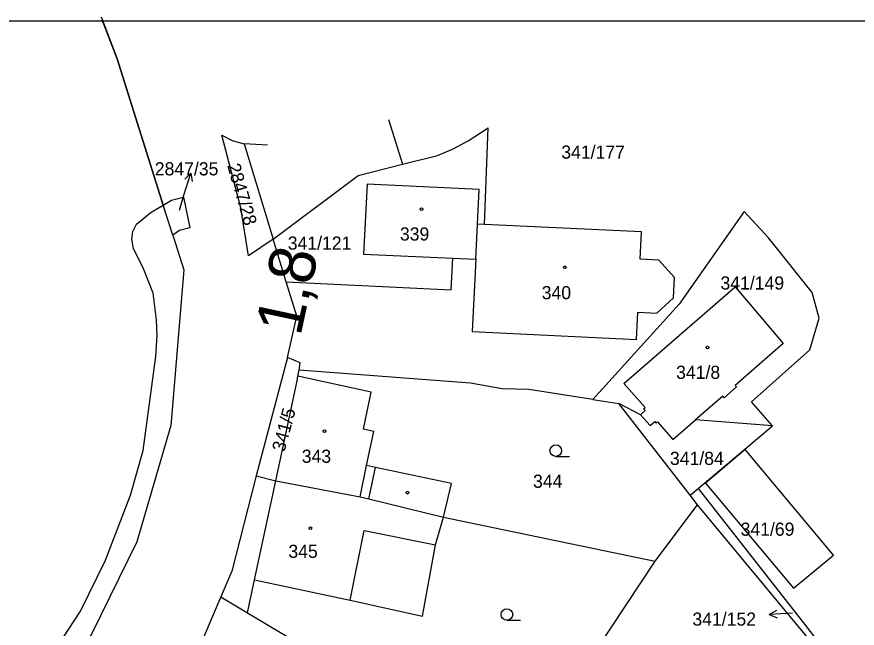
# Model space of a CAD drawing. Extents: x -558358 to -557517, y -1073786 to -1073189.
# Drawn here: x -558018.3 to -557909.7, y -1073268.6 to -1073189.6 of the extents above; entities that cross this region are included whole.
import ezdxf

# ---------------------------------------------------------------- set-up
doc = ezdxf.new("R2010")
doc.units = 0
for name, color, linetype in [('Hranice parcel', 7, 'Continuous'), ('Návěst místo trati', 7, 'Continuous'), ('Parcelní čísla', 7, 'Continuous'), ('Pop  PČ popisy', 7, 'Continuous'), ('Svazek obcí údolí Desné', 7, 'Continuous'), ('Vnitřní kresba', 7, 'Continuous'), ('Vrstva 1', 7, 'Continuous'), ('Značky budov', 7, 'Continuous'), ('Značky kultur', 7, 'Continuous')]:
    doc.layers.add(name, color=color, linetype=linetype)

msp = doc.modelspace()

# ---------------------------------------------------------------- linework, layer by layer
at = {"layer": 'Hranice parcel'}
for p, q in [((-557970.23, -1073202.86), (-557968.43, -1073208.63)), ((-557957.84, -1073216.4), (-557957.38, -1073203.94)), ((-557990.44, -1073205.56), (-557988.88, -1073205.99)), ((-557988.88, -1073205.99), (-557985.13, -1073218.31)), ((-557985.87, -1073206.17), (-557988.88, -1073205.99)), ((-557974.16, -1073210.07), (-557968.43, -1073208.63)), ((-557985.13, -1073218.31), (-557974.16, -1073210.07)), ((-557999.34, -1073213.91), (-557998.27, -1073213.29)), ((-558000.9, -1073214.81), (-557999.34, -1073213.91)), ((-557998.11, -1073217.81), (-557999.34, -1073213.91)), ((-557924.3, -1073214.73), (-557932.67, -1073226.72)), ((-557958.95, -1073220.92), (-557958.74, -1073216.36)), ((-557957.84, -1073216.4), (-557958.74, -1073216.36)), ((-557997.23, -1073217.21), (-557998.11, -1073217.81)), ((-557985.13, -1073218.31), (-557988.34, -1073220.45)), ((-557983.46, -1073223.81), (-557985.13, -1073218.31)), ((-557961.95, -1073220.78), (-557958.95, -1073220.92)), ((-557932.67, -1073226.72), (-557943.85, -1073239.02)), ((-557983.29, -1073233.62), (-557987.36, -1073248.89)), ((-557981.96, -1073236.04), (-557981.79, -1073235.24)), ((-557943.85, -1073239.02), (-557940.47, -1073239.54)), ((-557931.28, -1073251.41), (-557940.47, -1073239.54)), ((-557937.69, -1073241), (-557940.47, -1073239.54)), ((-557920.64, -1073242.45), (-557930.56, -1073241.68)), ((-557930.24, -1073250.53), (-557920.64, -1073242.45)), ((-557987.36, -1073248.89), (-557984.8, -1073249.54)), ((-557931.28, -1073251.41), (-557930.24, -1073250.53)), ((-557930.32, -1073252.64), (-557931.28, -1073251.41)), ((-557935.78, -1073259.94), (-557930.32, -1073252.64)), ((-557909.08, -1073278.25), (-557930.32, -1073252.64)), ((-557963.13, -1073254.23), (-557935.78, -1073259.94)), ((-557954.2, -1073287.72), (-557935.78, -1073259.94)), ((-557991.89, -1073264.55), (-557994.13, -1073269.82)), ((-557991.89, -1073264.55), (-557988.45, -1073266.61)), ((-557988.45, -1073266.61), (-557978.88, -1073272.32))]:
    msp.add_line(p, q, dxfattribs=at)
for points in [[(-558007.39, -1073189.57), (-558005.3, -1073194.99), (-557999.34, -1073213.91)], [(-557988.34, -1073220.45), (-557989.32, -1073214.27), (-557991.8, -1073204.87), (-557990.44, -1073205.56)], [(-557968.43, -1073208.63), (-557963.9, -1073207.49), (-557961.96, -1073206.66), (-557959.95, -1073205.6), (-557957.38, -1073203.94)], [(-557958.74, -1073216.36), (-557958.53, -1073211.88), (-557973.01, -1073211.21), (-557973.48, -1073220.25), (-557961.95, -1073220.78)], [(-557998.27, -1073213.29), (-557996.72, -1073212.87), (-557995.91, -1073216.87), (-557997.23, -1073217.21)], [(-557920.64, -1073242.45), (-557923.35, -1073239.36), (-557915.81, -1073232.62), (-557914.61, -1073228.54), (-557915.51, -1073225.19), (-557921.13, -1073218.15), (-557924.3, -1073214.73)], [(-557958.95, -1073220.92), (-557959.44, -1073230.26), (-557938.22, -1073231.3), (-557938.05, -1073227.77), (-557935.56, -1073227.89), (-557933.42, -1073225.91), (-557933.29, -1073223.26), (-557935.3, -1073221.04), (-557937.72, -1073220.92), (-557937.55, -1073217.37), (-557957.84, -1073216.4)], [(-557998.11, -1073217.81), (-557996.7, -1073222.28), (-557998.38, -1073242.39), (-558002.78, -1073257.43), (-558008.62, -1073269.37), (-558024.06, -1073293.44), (-558032.02, -1073303.96), (-558033.31, -1073305.78)], [(-557983.46, -1073223.81), (-557962.16, -1073224.87), (-557961.95, -1073220.78)], [(-557983.29, -1073233.62), (-557982.1, -1073228.28), (-557983.46, -1073223.81)], [(-557937.69, -1073241), (-557937.08, -1073240.47), (-557937.28, -1073240.24), (-557937.09, -1073240.08), (-557939.85, -1073236.97), (-557925.45, -1073224.49), (-557919.26, -1073231.82), (-557925.44, -1073237.21), (-557925.27, -1073237.41), (-557926.88, -1073238.81), (-557927.05, -1073238.61), (-557930.56, -1073241.68)], [(-557981.79, -1073235.24), (-557981.67, -1073234.3), (-557983.29, -1073233.62)], [(-557943.85, -1073239.02), (-557952.12, -1073237.75), (-557955.56, -1073237.67), (-557959.65, -1073236.94), (-557981.79, -1073235.24)], [(-557984.8, -1073249.54), (-557982.04, -1073236.64), (-557981.96, -1073236.04)], [(-557963.13, -1073254.23), (-557962.1, -1073249.91), (-557971.91, -1073247.83), (-557973.07, -1073247.59), (-557972.12, -1073243.17), (-557973.48, -1073242.88), (-557972.48, -1073238.09), (-557981.96, -1073236.04)], [(-557937.69, -1073241), (-557936.45, -1073242.42), (-557935.84, -1073241.9), (-557935.68, -1073242.09), (-557935.49, -1073241.92), (-557933.49, -1073244.23), (-557930.56, -1073241.68)], [(-557912.73, -1073259.16), (-557924.17, -1073245.52), (-557929.3, -1073249.85), (-557917.91, -1073263.41), (-557912.73, -1073259.16)], [(-557987.36, -1073248.89), (-557990.48, -1073261.24), (-557991.89, -1073264.55)], [(-557984.8, -1073249.54), (-557973.92, -1073251.6), (-557972.79, -1073251.88), (-557963.13, -1073254.23)], [(-557930.24, -1073250.53), (-557916.49, -1073268.06), (-557909.46, -1073277.19)], [(-557988.45, -1073266.61), (-557987.54, -1073262.34), (-557975.19, -1073264.98), (-557965.84, -1073267.06), (-557964.16, -1073257.82), (-557963.13, -1073254.23)]]:
    msp.add_lwpolyline(points, dxfattribs=at)
at = {"layer": 'Pop  PČ popisy'}
for p, q in [((-557996.68, -1073212.64), (-557995.8, -1073209.77)), ((-557995.8, -1073209.77), (-557996.57, -1073210.58)), ((-557995.8, -1073209.77), (-557995.62, -1073210.87)), ((-557997.26, -1073214.56), (-557996.68, -1073212.64)), ((-557921.05, -1073266.82), (-557920.07, -1073266.27)), ((-557918.05, -1073266.66), (-557921.05, -1073266.82)), ((-557921.05, -1073266.82), (-557920.02, -1073267.27))]:
    msp.add_line(p, q, dxfattribs=at)
at = {"layer": 'Svazek obcí údolí Desné'}
msp.add_lwpolyline([(-558066.74, -1073350.64), (-558065.9, -1073348.86), (-558061.08, -1073328.44), (-558060.65, -1073327.54), (-558046.7, -1073313.29), (-558030.4, -1073296.27), (-558015.33, -1073274.48), (-558010.02, -1073266.4), (-558006.82, -1073259.79), (-558003.58, -1073251.39), (-558001.93, -1073245.63), (-558000.3, -1073233.47), (-558000.14, -1073230.76), (-558000.21, -1073228.76), (-558000.67, -1073225.31), (-558001.93, -1073222.03), (-558003.18, -1073219.55), (-558003.41, -1073218.32), (-558003.28, -1073217.31), (-558002.8, -1073216.38), (-558000.9, -1073214.81), (-557999.34, -1073213.91), (-558005.3, -1073194.99), (-558007.24, -1073189.96)], dxfattribs=at)
at = {"layer": 'Vnitřní kresba'}
for p, q in [((-557973.92, -1073251.6), (-557973.07, -1073247.59)), ((-557972.79, -1073251.88), (-557971.91, -1073247.83)), ((-557987.54, -1073262.34), (-557984.8, -1073249.54)), ((-557975.19, -1073264.98), (-557973.4, -1073255.98)), ((-557973.4, -1073255.98), (-557964.16, -1073257.82))]:
    msp.add_line(p, q, dxfattribs=at)
at = {"layer": 'Vrstva 1'}
msp.add_line((-558357.53, -1073190.09), (-557516.53, -1073190.09), dxfattribs=at)
at = {"layer": 'Značky budov'}
for centre in [(-557965.99, -1073214.44), (-557947.45, -1073221.95), (-557929.04, -1073232.33), (-557978.51, -1073243.13), (-557967.78, -1073251.08), (-557980.34, -1073255.67)]:
    msp.add_circle(centre, 0.175, dxfattribs=at)
at = {"layer": 'Značky kultur'}
for p, q in [((-557948.63, -1073246.4), (-557946.88, -1073246.4)), ((-557954.95, -1073267.58), (-557953.2, -1073267.58))]:
    msp.add_line(p, q, dxfattribs=at)
for centre in [(-557948.63, -1073245.65), (-557954.95, -1073266.83)]:
    msp.add_circle(centre, 0.75, dxfattribs=at)

# ---------------------------------------------------------------- texts
at = {"layer": 'Návěst místo trati'}
msp.add_text('1,8', height=6, rotation=77.8693, dxfattribs=at).set_placement((-557981.63, -1073230.98))
at = {"layer": 'Parcelní čísla'}
for s, p in [('341/177', (-557947.92, -1073207.91)), ('2847/35', (-558000.44, -1073210.07)), ('339', (-557968.77, -1073218.49)), ('341/121', (-557983.26, -1073219.67)), ('341/149', (-557927.35, -1073224.83)), ('340', (-557950.45, -1073226.08)), ('341/8', (-557933.08, -1073236.37)), ('343', (-557981.45, -1073247.22)), ('341/84', (-557933.88, -1073247.5)), ('344', (-557951.57, -1073250.45)), ('341/69', (-557924.75, -1073256.65)), ('345', (-557983.18, -1073259.51)), ('341/152', (-557930.98, -1073268.27))]:
    msp.add_text(s, height=1.7, dxfattribs=at).set_placement(p)
for s, rotation, p in [('2847/28', 286, (-557991.1, -1073208.79)), ('341/5', 75, (-557983.69, -1073245.9))]:
    msp.add_text(s, height=1.7, rotation=rotation, dxfattribs=at).set_placement(p)

doc.saveas('drawing.dxf')
